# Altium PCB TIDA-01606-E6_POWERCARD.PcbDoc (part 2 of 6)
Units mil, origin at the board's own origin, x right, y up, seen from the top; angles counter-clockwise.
Board outline 13779.53 x 7874.02 mil, 4 copper layers (Top Layer, Gnd Layer, Pwr Layer, Bottom Layer), stack 94.4 mil thick; 550 components, 292 nets, 1594 pads, 572 vias.
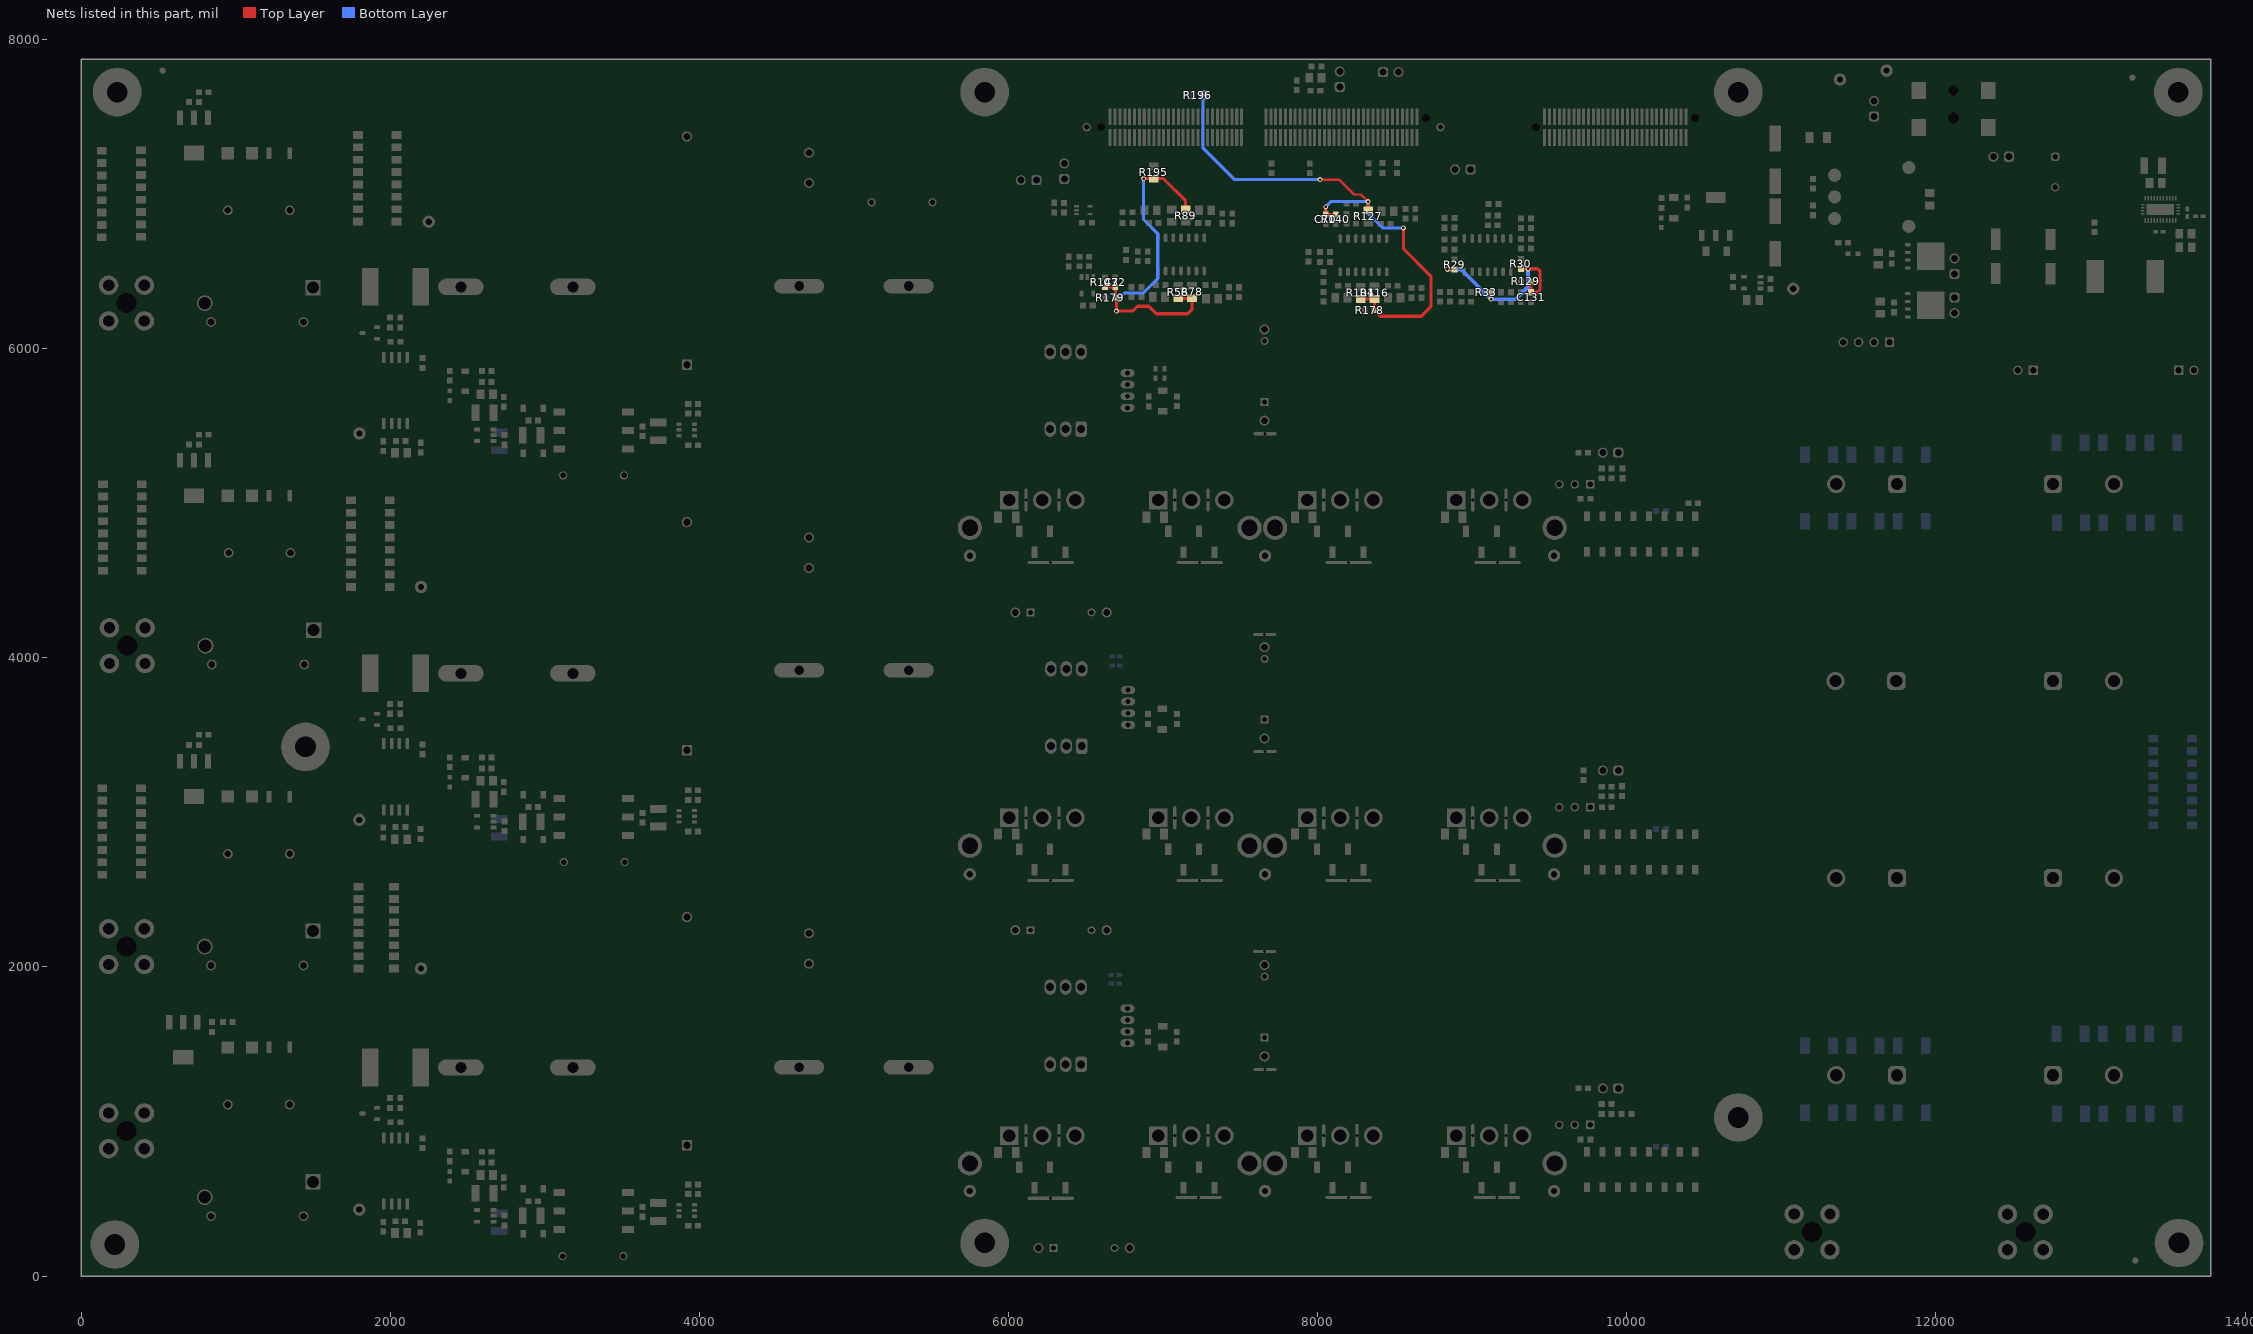
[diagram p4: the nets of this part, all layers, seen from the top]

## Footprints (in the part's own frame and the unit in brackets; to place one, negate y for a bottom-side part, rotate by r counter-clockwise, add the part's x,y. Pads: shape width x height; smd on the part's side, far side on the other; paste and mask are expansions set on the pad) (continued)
CASR [mm] "TH, 10-Leads, Body 13.4x21.91mm"
  rrect50% 1.9x2.54 hole 1.3: 1(1.37,6.35)
  oval 1.9x2.54 hole 1.3: 2(3.91,6.35) 3(6.45,6.35) 8(6.45,-6.35) 9(3.91,-6.35) 10(1.37,-6.35)
  oval 2.3x1.3 hole 0.8: 11(-6.25,-2.858) 12(-6.25,-0.953) 13(-6.25,0.952) 14(-6.25,2.857)
  body extent -7.8,-6.85 14.11,6.85, height 16.5
CE_Mark_5mm [mil] "Minimum text height for CE Mark"
  silkscreen extent -138,-98 138,98
controlCARD-120HSEC [mm] "Pads are not numbered according to Samtec datasheet."
  rect 0.5x2.724 smd: 1(-23.357,-1.678) 2(-23.357,1.722) 3(-22.557,-1.678) 4(-22.557,1.722) 5(-21.757,-1.678) 6(-21.757,1.722) 7(-20.957,-1.678) 8(-20.957,1.722) 9(-20.157,-1.678) 10(-20.157,1.722) 11(-19.357,-1.678) 12(-19.357,1.722) 13(-18.557,-1.678) 14(-18.557,1.722) 15(-17.757,-1.678) 16(-17.757,1.722) 17(-16.957,-1.678) 18(-16.957,1.722) 19(-16.157,-1.678) 20(-16.157,1.722) 21(-15.357,-1.678) 22(-15.357,1.722) 23(-14.557,-1.678) 24(-14.557,1.722) 25(-13.757,-1.678) 26(-13.757,1.722) 27(-12.957,-1.678) 28(-12.957,1.722) 29(-12.157,-1.678) 30(-12.157,1.722) 31(-11.357,-1.678) 32(-11.357,1.722) 33(-10.557,-1.678) 34(-10.557,1.722) 35(-9.757,-1.678) 36(-9.757,1.722) 37(-8.957,-1.678) 38(-8.957,1.722) 39(-8.157,-1.678) 40(-8.157,1.722) 41(-7.357,-1.678) 42(-7.357,1.722) 43(-6.557,-1.678) 44(-6.557,1.722) 45(-5.757,-1.678) 46(-5.757,1.722) 47(-4.957,-1.678) 48(-4.957,1.722) 49(-4.157,-1.678) 50(-4.157,1.722) 51(-3.357,-1.678) 52(-3.357,1.722) 53(-2.557,-1.678) 54(-2.557,1.722) 55(-1.757,-1.678) 56(-1.757,1.722) 57(2.243,-1.678) 58(2.243,1.722) 59(3.043,-1.678) 60(3.043,1.722) 61(3.843,-1.678) 62(3.843,1.722) 63(4.643,-1.678) 64(4.643,1.722) 65(5.443,-1.678) 66(5.443,1.722) 67(6.243,-1.678) 68(6.243,1.722) 69(7.043,-1.678) 70(7.043,1.722) 71(7.843,-1.678) 72(7.843,1.722) 73(8.643,-1.678) 74(8.643,1.722) 75(9.443,-1.678) 76(9.443,1.722) 77(10.243,-1.678) 78(10.243,1.722) 79(11.043,-1.678) 80(11.043,1.722) 81(11.843,-1.678) 82(11.843,1.722) 83(12.643,-1.678) 84(12.643,1.722) 85(13.443,-1.678) 86(13.443,1.722) 87(14.243,-1.678) 88(14.243,1.722) 89(15.043,-1.678) 90(15.043,1.722) 91(15.843,-1.678) 92(15.843,1.722) 93(16.643,-1.678) 94(16.643,1.722) 95(17.443,-1.678) 96(17.443,1.722) 97(18.243,-1.678) 98(18.243,1.722) 99(19.043,-1.678) 100(19.043,1.722) 101(19.843,-1.678) 102(19.843,1.722) 103(20.643,-1.678) 104(20.643,1.722) 105(21.443,-1.678) 106(21.443,1.722) 107(22.243,-1.678) 108(22.243,1.722) 109(23.043,-1.678) 110(23.043,1.722) 111(23.843,-1.678) 112(23.843,1.722) 113(24.643,-1.678) 114(24.643,1.722) 115(25.443,-1.678) 116(25.443,1.722) 117(26.243,-1.678) 118(26.243,1.722) 119(27.043,-1.678) 120(27.043,1.722)
  round 0.025 hole 1.27 unplated mask+0.876: 181(-24.857,0.022) 182(28.543,1.522)
  round 1.348 hole 0.84: 185(-27.207,0.022) 186(30.893,0.022)
  silkscreen extent -32.11,-3.86 35.8,3.9, body extent -31.75,-3.48 35.3,3.52, height 12.35
controlCARD-180HSEC-60pinAddon [mm] "Pads are not numbered according to datasheet."
  round 0.025 hole 1.27 unplated mask+0.876: 61(-13.1,0) 62(13.1,1.5)
  rect 0.5x2.724 smd: 121(-11.6,-1.7) 122(-11.6,1.7) 123(-10.8,-1.7) 124(-10.8,1.7) 125(-10,-1.7) 126(-10,1.7) 127(-9.2,-1.7) 128(-9.2,1.7) 129(-8.4,-1.7) 130(-8.4,1.7) 131(-7.6,-1.7) 132(-7.6,1.7) 133(-6.8,-1.7) 134(-6.8,1.7) 135(-6,-1.7) 136(-6,1.7) 137(-5.2,-1.7) 138(-5.2,1.7) 139(-4.4,-1.7) 140(-4.4,1.7) 141(-3.6,-1.7) 142(-3.6,1.7) 143(-2.8,-1.7) 144(-2.8,1.7) 145(-2,-1.7) 146(-2,1.7) 147(-1.2,-1.7) 148(-1.2,1.7) 149(-0.4,-1.7) 150(-0.4,1.7) 151(0.4,-1.7) 152(0.4,1.7) 153(1.2,-1.7) 154(1.2,1.7) 155(2,-1.7) 156(2,1.7) 157(2.8,-1.7) 158(2.8,1.7) 159(3.6,-1.7) 160(3.6,1.7) 161(4.4,-1.7) 162(4.4,1.7) 163(5.2,-1.7) 164(5.2,1.7) 165(6,-1.7) 166(6,1.7) 167(6.8,-1.7) 168(6.8,1.7) 169(7.6,-1.7) 170(7.6,1.7) 171(8.4,-1.7) 172(8.4,1.7) 173(9.2,-1.7) 174(9.2,1.7) 175(10,-1.7) 176(10,1.7) 177(10.8,-1.7) 178(10.8,1.7) 179(11.6,-1.7) 180(11.6,1.7)
  silkscreen extent -14.68,-3.88 14.68,3.88, body extent -14.3,-3.5 14.3,3.5, height 7.95
CUI_PJ-002AH-SMT [mm] "CUI"
  rect 2.8x2.4 smd: 1(-3.05,5.7) 1A(3.05,5.7) 2(-3.05,-5.7) 3(3.05,-5.7)
  round 1 hole 1.6 unplated: MH1(-3.05,0)
  round 1.524 hole 1.8 unplated: MH2(1.45,0)
  silkscreen extent -8.05,-4.5 6.75,5.45, body extent -8.05,-6.3 6.75,6.3, height 11.2
D0014A_N [mm] "SOIC, 14-Leads, Body 8.7x3.9mm, Pitch 1.27mm, IPC Medium Density"
  oval 1.45x0.6 smd: 1(-2.725,3.81) 2(-2.725,2.54) 3(-2.725,1.27) 4(-2.725,0) 5(-2.725,-1.27) 6(-2.725,-2.54) 7(-2.725,-3.81) 8(2.725,-3.81) 9(2.725,-2.54) 10(2.725,-1.27) 11(2.725,0) 12(2.725,1.27) 13(2.725,2.54) 14(2.725,3.81)
  silkscreen extent -3.3,-4.4 0.9,4.4, body extent -3.02,-4.32 3.02,4.32, height 1.6
DBV0005A_N [mm] "SOT23, 5-Leads, Body 2.9x1.6mm, Pitch 0.95mm, Lead Span 2.8mm, IPC Medium Density"
  rrect17% 1x0.6 smd: 1(-1.375,0.95) 2(-1.375,0) 3(-1.375,-0.95) 4(1.375,-0.95) 5(1.375,0.95)
  silkscreen extent -0.25,-1.55 0.25,1.55, body extent -1.42,-1.46 1.42,1.46, height 1.09
DBV0006A_L [mm] "SOT23, 6-Leads, Body 2.9x1.6mm, Pitch 0.95mm, Lead Span 2.8mm, IPC High Density"
  rrect18% 0.8x0.55 smd: 1(-1.275,0.95) 2(-1.275,0) 3(-1.275,-0.95) 4(1.275,-0.95) 5(1.275,0) 6(1.275,0.95)
  silkscreen extent -1.55,-1.53 0.55,1.53, body extent -1.42,-1.46 1.42,1.46, height 1.12
DCK0005A_N [mm] "SOT353, 5-Leads, Body 2x1.3mm, Pitch 0.65mm, Lead Span 2.1mm, IPC Medium Density"
  rrect25% 0.85x0.4 smd: 1(-1.125,0.65) 2(-1.125,0) 3(-1.125,-0.65) 4(1.125,-0.65) 5(1.125,0.65)
  silkscreen extent -1.48,-1.02 0.55,1.1, body extent -1.14,-1 1.14,1, height 0.95
DCY0004A_N [mm] "SOT223/SC73, 4-Leads, Body 6.5x3.5mm, Pitch 2.3mm, Lead Span 7mm, IPC Medium Density"
  rrect11% 1.75x0.9 smd: 1(-3.125,2.3) 2(-3.125,0) 3(-3.125,-2.3)
  rrect6% 1.75x3.2 smd: 4(3.125,0)
  silkscreen extent -3.02,-3.35 1.4,3.47, body extent -3.48,-3.25 3.48,3.25, height 1.68
DDC0005A_N [mm]
  rrect17% 1x0.6 smd: 1(-1.375,0.95) 2(-1.375,0) 3(-1.375,-0.95) 4(1.375,-0.95) 5(1.375,0.95)
  silkscreen extent -1.25,-1.52 0.88,1.57, body extent -1.41,-1.45 1.41,1.45, height 1.1
DQJ0008A [mm] "SMD, 8-Leads, Body 5.75x4.9mm"
  rrect39% 0.91x0.51 smd paste-0.05 mask-0.05: 1(-2.795,1.905) 2(-2.795,0.635) 3(-2.795,-0.635) 4(-2.795,-1.905) 5(2.795,-1.905) 6(2.795,-0.635) 7(2.795,0.635) 8(2.795,1.905)
  rrect8% 1.58x1.25 on Top Paste: 9(-0.38,-1.45) 9(-0.38,0) 9(-0.38,1.45) 9(1.4,-1.45) 9(1.4,0) 9(1.4,1.45)
  rrect3% 3.48x4.47 on Top Solder: 9(0.55,0)
  rrect2% 4.49x4.57 smd paste-2.5 mask-2.5: 9(1.005,0)
  silkscreen extent -3,-2.6 3,2.6, body extent -3.13,-2.45 3.13,2.45, height 1.15
DWV0008A [mm] "SOIC, 8-Leads, Body 5.95x7.6mm (max), Pitch 1.27mm"
  rrect17% 1.8x0.6 smd: 1(-5.45,1.905) 2(-5.45,0.635) 3(-5.45,-0.635) 4(-5.45,-1.905) 5(5.45,-1.905) 6(5.45,-0.635) 7(5.45,0.635) 8(5.45,1.905)
  silkscreen extent -6.25,-2.95 2.98,2.95, body extent -5.77,-2.92 5.77,2.93, height 2.67
EMC2 [mm] "Welwyn"
  round 1.6 hole 1.1: 1(-7.6,0) 2(7.6,0)
  silkscreen extent -6.42,-2 6.42,2, body extent -8.02,-2 8.02,2, height 4
ESD_Overlay_Medium [mil]
  silkscreen extent -127,-109 125,110
EUG0005A [mm] "Module, 5-Leads, Body 15.24x12.7mm"
  round 2.16 smd: 1(-6.095,3.56) 2(-6.095,0) 3(-6.095,-3.56) 4(6.095,-4.825) 5(6.095,4.825)
  silkscreen extent -8.63,-6.35 7.62,6.35, body extent -7.63,-6.35 7.62,6.35, height 8.76
FCC_disclaimer [mil]
Fiducial10-30 [mm]
  round 1 smd mask+1: 1(0,0)
  Top Layer keep-out circle w1.678: c0,0 r0.75
FP-C3M0060065D_TO-247-3-MFG [mil]
  rrect3% 120x120 hole 80 paste-39370.1 mask+0: 1(-8.37,214)
  round 120 hole 80 paste-39370.1 mask+0: 2(-8.37,0) 3(-8.37,-214)
  silkscreen extent -103,-318 103,343, body extent -99,-314 99,314, height 1004
FP-C3M0075120D_TO-247-3-MFG [mil]
  rrect3% 120x120 hole 80 paste-39370.1 mask+0: 1(-8.37,214)
  round 120 hole 80 paste-39370.1 mask+0: 2(-8.37,0) 3(-8.37,-214)
  silkscreen extent -103,-318 103,343, body extent -99,-314 99,314, height 1004
FP-ERJ-PB3B1003V_0603-MFG [mm]
  rrect15% 0.65x0.9 smd paste+0 mask+0: 1(-0.725,0) 2(0.725,0)
  silkscreen extent 0,-0.48 0,0.48, body extent -0.8,-0.4 0.8,0.4, height 0.55
FP-PSR400ITQFJ2L00_3921-MFG [mm]
  rrect4% 2.7x6.2 smd paste+0 mask+0: 1(-4.15,0) 2(4.15,0)
  silkscreen extent -2.42,-2.75 2.42,2.75, body extent -5.6,-3.2 5.6,3.2, height 0.25
HSINK_OMNI-UNI-18-50 [mm] "Heat Sink, TO-247, TO-264"
  round 4 hole 2.67: 1(-22.97,0) 2(22.97,0)
  body extent -25,-11.66 25,6.37, height 35.6
IEC_Caution_Medium [mil]
  silkscreen extent -217,-182 217,193
IEC_HighVoltage_Medium [mil]
  silkscreen extent -217,-176 217,200
IEC_HotSurface_Medium [mil]
  silkscreen extent -217,-188 217,188
Keystone5000#1 [mil] "For Keystone 500x miniature loop terminals"
  round 80 hole 40: 1(0,0)
  silkscreen extent -52,-52 52,52, body extent -49,-49 49,49, height 182
Keystone5000#2 [mil] "For Keystone 500x miniature loop terminals"
  round 80 hole 40: 1(0,-0.67)
  silkscreen extent -52,-52 52,52, body extent -49,-49 49,49, height 182
Keystone5002 [mil] "For Keystone 500x miniature loop terminals"
  round 80 hole 40: 1(0,0)
  silkscreen extent -52,-52 52,52, body extent -49,-49 49,49, height 182
Keystone24438 [mil] "Standoff, Aluminium, M3x0.5mm, L 25 mm"
  round 1 on Mech4: 0(0,0)
  body extent -98,-114 98,114, height 984
Label_650x200 [mil] "Thermal Transfer Label"
  round 1 on Mech13: 0(0,0)
  silkscreen extent -325,-100 325,100, body extent -325,-100 325,100, height 1
LP0003A [mm] "TO, Flat Index; 3 In-Line, Formed Axial Leads; Body Dia. 4.8mm; Leads 0.56 x 0.41 mm (max)"
  rrect7% 1.4x1.4 hole 0.9: 1(0,2.54)
  round 1.4 hole 0.9: 2(0,0) 3(0,-2.54)
  silkscreen extent -1.35,-2.41 2.65,2.95, body extent -1.33,-2.83 2.35,2.83, height 9.01
MiniMELF [mil] "SMD, 2-Leads, Dia 59mil"
  rect 30x75 smd: 1(-67.5,0) 2(67.5,0)
  silkscreen extent -44,-30 40,30, body extent -73,-30 73,30, height 59
Nichicon_3000x4500_Snap [mm] "TH, 2-Leads, Dia 30mm, Pin Spacing 10mm"
  rrect50% 3x3 hole 2: 1(-5,0)
  round 3 hole 2: 2(5,0)
  silkscreen extent -15.75,-15.75 15.75,15.75, body extent -15.75,-15.75 15.76,15.75, height 47.01
Pb-Free_Overlay_Medium [mil]
  silkscreen extent -95,-95 95,95
Relay_T9AS1D12 [mm] "TH, 4-Leads, Body 32.51x27.43mm"
  rect 2.5x2.5 hole 1.98: 1(-8.89,5.08)
  round 2.6 hole 2.06: 2(8.89,7.62)
  round 1.6 hole 1.09: 3(-5.08,-7.62) 4(5.08,-7.62)
  silkscreen extent -13.79,-14.73 14.15,17.79, body extent -13.26,-14.73 14.17,17.78, height 20.45
RNP0030B [mm] "QFN, 30-Leads, Body 6x4mm, Pitch 0.5mm, Thermal Pad 1.8x4.5mm"
  rrect40% 0.75x0.25 smd: 1(-1.825,2.5) 2(-1.825,2) 3(-1.825,1.5) 4(-1.825,1) 5(-1.825,0.5) 6(-1.825,0) 7(-1.825,-0.5) 8(-1.825,-1) 9(-1.825,-1.5) 10(-1.825,-2) 11(-1.825,-2.5) 16(1.825,-2.5) 17(1.825,-2) 18(1.825,-1.5) 19(1.825,-1) 20(1.825,-0.5) 21(1.825,0) 22(1.825,0.5) 23(1.825,1) 24(1.825,1.5) 25(1.825,2) 26(1.825,2.5)
  rrect40% 0.25x0.6 smd: 12(-0.75,-2.9) 13(-0.25,-2.9) 14(0.25,-2.9) 15(0.75,-2.9) 27(0.75,2.9) 28(0.25,2.9) 29(-0.25,2.9) 30(-0.75,2.9)
  rrect12% 0.8x0.94 on Top Paste: 31(-0.5,1.71) 31(-0.5,-0.57) 31(-0.5,0.57) 31(-0.5,-1.71) 31(0.5,1.71) 31(0.5,-0.57) 31(0.5,0.57) 31(0.5,-1.71)
  rrect5% 1.8x4.5 smd paste-3: 31(0,0)
  silkscreen extent -2.17,-3.18 2.18,3.17, body extent -2,-3 2,3, height 0.8
Samtec_SSW-102-01-x-S [mm] "Receptacle, 2x1, 2.54mm, TH"
  rect 1.55x1.55 hole 1.04: 1(-1.27,0)
  round 1.55 hole 1.04: 2(1.27,0)
  silkscreen extent -3.1,-1.21 2.79,1.21, body extent -2.79,-1.21 2.8,1.2, height 8.51
SMA [mm] "Molded Diode, 2-Leads, Body 4.3x2.6mm, IPC Medium Density, based on OnSemi component dimensions and land pattern"
  rect 2x2 smd: 1(-2,0) 2(2,0)
  silkscreen extent -3.66,-1.57 2.79,1.57, body extent -2.6,-1.3 2.6,1.3, height 2.42
SOD-123 [mm] "On Semi recommended land pattern"
  rect 0.915x1.22 smd: 1(-1.637,0) 2(1.637,0)
  silkscreen extent -2.74,-1.17 2.03,1.17, body extent -1.93,-0.9 1.93,0.9, height 1.35
SOT-23 [mm] "SOT23, 3-Leads, Body 2.9x1.3mm, Pitch 0.95mm, Lead Span 2.5mm, IPC Medium Density"
  rrect50% 1x0.6 smd: 1(-1.2,0.95) 2(-1.2,-0.95) 3(1.2,0)
  silkscreen extent -1.62,-1.5 0.7,1.5, body extent -1.16,-1.45 1.21,1.45, height 1
SOT-223 [mm] "SOT223/SC73, 4-Leads, Body 6.5x3.5mm, Pitch 2.3mm, Lead Span 7mm, IPC Medium Density"
  rrect10% 2.4x1 smd: 1(-2.9,2.3) 2(-2.9,0) 3(-2.9,-2.3)
  rrect4% 2.4x3.3 smd: 4(2.9,0)
  silkscreen extent -3.33,-3.35 1.4,3.35, body extent -3.5,-3.25 3.5,3.25, height 1.62
SQM_7 [mm] "TH, 2-Leads, Body 13x9mm, Pin Spacing 5mm"
  round 1.65 hole 1.1: 1(-2.5,0) 2(2.5,0)
  silkscreen extent -7,-5.25 7,5.25, body extent -7,-5.25 7,5.25, height 40
Sullins_xPxC041KFXC-RC [mm] "Receptacle, 2.54mm, 4x1, SMT"
  rrect10% 1x1.9 smd: 1(-3.81,1.7) 2(-1.27,-1.7) 3(1.27,1.7) 4(3.81,-1.7)
  body extent -5.08,-2.15 5.08,2.15, height 7.5
Sullins_xPxC041LFBN [mm] "Receptacle, 2.54mm, 4x1, TH"
  rect 1.55x1.55 hole 1.02: 1(-3.81,0)
  round 1.55 hole 1.02: 2(-1.27,0) 3(1.27,0) 4(3.81,0)
  silkscreen extent -5.33,-1.27 5.33,1.6, body extent -5.33,-1.27 5.33,1.27, height 8.5
Sullins_xPxC082KFMS-RC [mm] "Receptacle, 2.54mm, 8x2, SMT"
  rrect10% 1x1.56 smd: 1(-8.89,2.905) 2(-8.89,-2.905) 3(-6.35,2.905) 4(-6.35,-2.905) 5(-3.81,2.905) 6(-3.81,-2.905) 7(-1.27,2.905) 8(-1.27,-2.905) 9(1.27,2.905) 10(1.27,-2.905) 11(3.81,2.905) 12(3.81,-2.905) 13(6.35,2.905) 14(6.35,-2.905) 15(8.89,2.905) 16(8.89,-2.905)
  body extent -10.41,-3.42 10.41,3.42, height 7.5
VY1_900x500x1300 [mm] "TH, Body 9x5mm, PinSpacing 10mm"
  round 1.35 hole 0.9: 1(-5,0) 2(5,0)
  body extent -5.4,-2.5 5.4,2.5, height 12.93
WCAP-ASLL_800x1050 [mm] "SMD, 2-Leads, Dia 8mm"
  rrect5% 4.2x1.9 smd: 1(-3.5,0) 2(3.5,0)
  body extent -4.3,-4.25 4.3,4.25, height 10.51
WCAP-ATLI_1000x1600 [mm] "TH, 2-Leads, Dia 10mm, Pin Spacing 5mm"
  rrect50% 1.35x1.35 hole 0.9: 1(-2.5,0)
  round 1.35 hole 0.9: 2(2.5,0)
  body extent -5.25,-5.25 5.26,5.25, height 17.51
WCAP-FTBP_1800x700x1300 [mm] "TH, 2-Leads, Body 18x7mm, Lead Spacing 15mm"
  round 1.65 hole 1.1: 1(-7.5,0) 2(7.5,0)
  body extent -9.75,-4 9.75,4, height 14
WCAP-PSLP_630x580 [mm] "SMD, 2-Leads, Dia 6.3mm"
  rect 3.5x1.6 smd: 1(-2.8,0) 2(2.8,0)
  silkscreen extent -3.4,-3.4 3.4,3.4, body extent -3.4,-3.4 3.4,3.4, height 5.81
WE-PD_1210 [mm] "Wurth Elektronik recommended land pattern"
  rect 2.9x5.4 smd: 1(-4.95,0) 2(4.95,0)
  silkscreen extent -6,-6 6,6, body extent -6,-6 6,6, height 10.01
WEEE_Minimum [mil] "WEEElie bin"
  silkscreen extent -95,-172 99,104
WL-SMCD-0603 [mm] "SMD, 2-Leads, Body 1.6x0.8mm"
  rrect13% 0.8x0.75 smd: 1(-0.8,0) 2(0.8,0)
  body extent -0.8,-0.4 0.8,0.4, height 0.4
Wurth_750313638 [mm] "SMD, 6-Leads, Body 8x9.14mm, Pitch 3.05mm"
  rect 1.9x1.14 smd: 1(-5.655,3.05) 2(-5.655,0) 3(-5.655,-3.05) 4(5.655,-3.05) 5(5.655,0) 6(5.655,3.05)
  silkscreen extent -4,-4.57 4,4.87, body extent -6.35,-4.57 6.35,4.57, height 7.62
WURTH_61300211121 [mm] "Header, 2.54mm, 2x1, TH"
  rrect50% 1.65x1.65 hole 1.15: 1(-1.27,0)
  round 1.65 hole 1.15: 2(1.27,0)
  body extent -2.54,-1.27 2.54,1.27, height 8.54
Wurth_WP-THRBU [mm] "Power Element Bush, M3, TH"
  round 3.2 hole 1.85: 1(-2.935,-2.935) 1(-2.935,2.935) 1(2.935,-2.935) 1(2.935,2.935)
  round 3.1 on Top Paste: ""(-2.935,-2.935) ""(-2.935,2.935) ""(2.935,-2.935) ""(2.935,2.935)
  round 3 hole 3.3 unplated mask+0.102: ""(0,0)
  silkscreen extent -3.5,-3.5 3.5,3.5, body extent -3.5,-3.5 3.5,3.5, height 3

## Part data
C1 C2 C3 C11 C12 C13: library part CMP-0081646-1, "CAP, Film, 0.15 µF, 630 V,+/- 5%, 0.06122 ohm, TH", Cap_Case=18x7x13mm, Manufacturer="Wurth Elektronik", Supplier Part Number 1=732-11835-ND, Tolerance_%=5%, Value1="0.06122 ohm", Value2=630V, ValueDisplayed=0.15µF
C4 C5 C6 C7 C73 C74 C75 C76: library part CMP-0010058-3, "CAP, AL, 120 uF, 600 V, +/- 20%, TH", Cap_Case=30x45mm, Manufacturer=Nichicon, Supplier Part Number 1=493-14690-ND, Tolerance_%=20%, Value1=Unknown, Value2=600V, ValueDisplayed=120uF
C8 C9 C10: library part CMP-0083863-1, "CAP, Film, 10 µF,  V,+/- 10%, AEC-Q200 Grade 1, TH", Cap_Case=41.5x28mm, Manufacturer=TDK, Supplier Part Number 1=495-4794-ND, Tolerance_%=10%, ValueDisplayed=10µF
C14 C18 C21 C23 C25 C28 C29 C32 C35 C36 C39 C40 C41 C42 C44 C45 C46 C47 C50 C51 C52 C53 C54 C55 C57 C59 C60 C63 C69 C70 C71 C72 C90 C91 C92 C131 C132 C134 C135: library part CMP-0006979-5, "CAP, CERM, 0.1 uF, 25 V, +/- 10%, X7R, 0603", Cap_Case=0603, Manufacturer=Kemet, Supplier Part Number 1=399-5345-1-ND, TempCo=X7R, Tolerance_%=10%, Value1=Unknown, Value2=25V, ValueDisplayed=0.1uF
C15 C20 C30 C38: library part CMP-0008132-2, "CAP, CERM, 2.2 uF, 10 V, +/- 10%, X5R, 0805", Cap_Case=0805, Manufacturer=MuRata, Supplier Part Number 1=490-1704-1-ND, TempCo=X5R, Tolerance_%=10%, Value1="0.009 ohm", Value2=10V, ValueDisplayed=2.2uF
C16 C17 C93 C95 C97 C98 C105 C106 C107 C110 C112 C116: library part CMP-0009233-2, "CAP, CERM, 10 uF, 35 V, +/- 10%, X7R, 1210", Cap_Case=1210, Manufacturer=MuRata, Supplier Part Number 1=490-5314-1-ND, TempCo=X7R, Tolerance_%=10%, Value1=Unknown, Value2=35V, ValueDisplayed=10uF
C19: library part CMP-0006551-2, "CAP, CERM, 0.47 uF, 6.3 V, +/- 10%, X5R, 0402", Cap_Case=0402, Manufacturer=MuRata, Supplier Part Number 1=490-3266-1-ND, TempCo=X5R, Tolerance_%=10%, Value1=Unknown, Value2=6.3V, ValueDisplayed=0.47uF
C22 C24 C31 C43 C49: library part CMP-0080740-1, "CAP, CERM, 10 µF, 25 V,+/- 10%, X7R, 1206", Cap_Case=1206, Manufacturer=TDK, Supplier Part Number 1=445-7705-1-ND, TempCo=X7R, Tolerance_%=10%, Value2=25V, ValueDisplayed=10µF
C26 C27 C33 C34 C64 C66 C94 C96 C99 C100 C103 C104 C108 C109 C111 C113 C115: library part CMP-0079602-1, "CAP, CERM, 0.1 µF, 50 V,+/- 10%, X7R, AEC-Q200 Grade 1, 0603", Cap_Case=0603, Manufacturer=Kemet, Supplier Part Number 1=399-6856-1-ND, TempCo=X7R, Tolerance_%=10%, Value2=50V, ValueDisplayed=0.1µF
C37 C56 C58 C117: library part CMP-0006867-4, "CAP, CERM, 1 uF, 25 V, +/- 10%, X7R, 0603", Cap_Case=0603, Manufacturer=Kemet, Supplier Part Number 1=399-7376-1-ND, TempCo=X7R, Tolerance_%=10%, Value1=Unknown, Value2=25V, ValueDisplayed=1uF
C48 C126: library part CMP-0081645-1, "CAP, Aluminum Polymer, 33 µF, 20 V,+/- 20%, 0.03 ohm, D6.3xL5.8mm SMD", Cap_Case=6.3x5.8mm, Manufacturer="Wurth Elektronik", Supplier Part Number 1=732-6430-1-ND, Tolerance_%=20%, Value1="0.03 ohm", Value2=20V, ValueDisplayed=33µF
C61 C62: library part CMP-0081644-1, "CAP, AL, 100 µF, 50 V, +/- 20%, SMD", Cap_Case=8X10.5mm, Manufacturer="Wurth Elektronik", Supplier Part Number 1=732-8550-1-ND, Tolerance_%=20%, Value2=50V, ValueDisplayed=100µF
C65 C67 C68: library part CMP-0086097-1, "CAP, CERM, 1000 pF, X1 760 VAC/Y1 500 VAC, +/- 20%, Y5U, 9x5mm", Cap_Case=9X5mm, Manufacturer=Vishay-Bccomponents, TempCo=Y5U, Tolerance_%=20%, ValueDisplayed=1000pF
C77 C79 C81 C118: library part CMP-0083857-1, "CAP, CERM, 100 pF, 50 V,+/- 10%, X7R, 0603", Cap_Case=0603, Manufacturer="Samsung Electro-Mechanics", TempCo=X7R, Tolerance_%=10%, Value2=50V, ValueDisplayed=100pF
C78 C80 C82: library part CMP-0006799-4, "CAP, CERM, 82 pF, 50 V, +/- 5%, C0G/NP0, 0603", Cap_Case=0603, Manufacturer=AVX, Supplier Part Number 1=478-1174-1-ND, TempCo=C0G/NP0, Tolerance_%=5%, Value1="0.131 ohm", Value2=50V, ValueDisplayed=82pF
C83 C84 C85 C86 C87 C88 C133: library part CMP-0006762-4, "CAP, CERM, 100 pF, 50 V, +/- 1%, C0G/NP0, 0603", Cap_Case=0603, Manufacturer=AVX, Supplier Part Number 1=478-6202-1-ND, TempCo=C0G/NP0, Tolerance_%=1%, Value1=Unknown, Value2=50V, ValueDisplayed=100pF
C89: library part CMP-0081643-1, "CAP, AL, 220 µF, 50 V, +/- 20%, TH", Cap_Case=10x16mm, Manufacturer="Wurth Elektronik", Supplier Part Number 1=732-9057-1-ND, Tolerance_%=20%, Value2=50V, ValueDisplayed=220µF
C101 C102 C114 C125: library part CMP-0008309-2, "CAP, CERM, 4.7 uF, 50 V, +/- 10%, X5R, 0805", Cap_Case=0805, Manufacturer=MuRata, Supplier Part Number 1=GRM21BR61H475KE51L-ND, TempCo=X5R, Tolerance_%=10%, Value1=Unknown, Value2=50V, ValueDisplayed=4.7uF
C119: library part CMP-0083861-1, "CAP, CERM, 0.47 µF, 50 V,+/- 10%, X5R, 0603", Cap_Case=0603, Manufacturer=MuRata, Supplier Part Number 1=490-11994-1-ND, TempCo=X5R, Tolerance_%=10%, Value2=50V, ValueDisplayed=0.47µF
C120 C121 C122 C127 C128 C129: library part CMP-0012400-3, "CAP, Film, 0.068 uF, 630 V, +/- 10%, TH", Manufacturer=TDK, Supplier Part Number 1=1781890, Tolerance_%=10%, Value1=Unknown, Value2=630V, ValueDisplayed=0.068uF
C123: library part CMP-0082268-1, "CAP, CERM, 4.7 µF, 100 V,+/- 10%, X7S, AEC-Q200 Grade 1, 1210", Cap_Case=1210, Manufacturer=MuRata, Supplier Part Number 1=490-14484-1-ND, TempCo=X7S, Tolerance_%=10%, Value1="0.001 ohm", Value2=100V, ValueDisplayed=4.7µF
C124: library part CMP-0008373-2, "CAP, CERM, 0.047 uF, 100 V, +/- 10%, X7R, 0805", Cap_Case=0805, Manufacturer=MuRata, Supplier Part Number 1=490-3325-1-ND, TempCo=X7R, Tolerance_%=10%, Value1=Unknown, Value2=100V, ValueDisplayed=0.047uF
C130: library part CMP-0009601-2, "CAP, CERM, 2200 pF, 3KV, +/- 20%, E, Cap, 7x12x9 mm", Cap_Case=CAPRD1000W60D900H1200, Manufacturer=MuRata, Supplier Part Number 1=490-7047-ND, TempCo=E, Tolerance_%=20%, Value1=Unknown, Value2=250V, ValueDisplayed=2200pF
D1 D2 D4 D5: library part CMP-0006039-4, "Diode, Zener, 15 V, 500 mW, MiniMELF", Manufacturer="Micro Commercial Components", Power_W=500mW, Value1=0.5W
D3 D6 D7 D8: library part CMP-0028389-2, "Diode, Schottky, 60 V, 1 A, SMA", Manufacturer="Diodes Inc.", Value1=1A, Value2=0.7V
D9 D11 D24 D25 D30 D31: library part CMP-0080707-2, "Diode, Schottky, 20 V, 0.5 A, SOD-123", Manufacturer="Diodes Inc.", Value1=0.5A, Value2=0.33V
D12 D14 D16: library part CMP-0005922-4, "Diode, TVS, Uni, 27 V, SOT-23", Manufacturer="ON Semiconductor", Value1=40W
D13 D15 D17: library part CMP-0005926-4, "Diode, TVS, Uni, 33 V, 46 Vc, SOT-23", Manufacturer="ON Semiconductor", Value1=40W
D18 D19 D26 D27 D32: library part CMP-0081648-2, "LED, Green, SMD", Color=Green, Manufacturer="Wurth Elektronik", Power_TotalModule=48mW, Value1=0.048W, Value2=2V
D28 D29 D33: library part CMP-0005803-3, "Diode, Zener, 5.6 V, 500 mW, SOD-123", Manufacturer="Diodes Inc.", Power_W=500mW, Value1=0.5W
FID1 FID2 FID3 FID4 FID5 FID6: library part CMP-0077181-1, "Fiducial mark.  There is nothing to buy or mount.", Manufacturer=N/A
GND_1 GND_2 GND_3 TP1 TP4 TP5 TP6 TP7 TP8 TP9 TP10 TP11 TP12 TP13 TP14 TP15: library part CMP-0055137-1, "Test Point, Miniature, Red, TH", Color=Red, Manufacturer=Keystone, Supplier Part Number 1=36-5000-ND
H1 H2 H3 H4 H9 H10 H11 H12 H13: library part CMP-0003646-1, "MACHINE SCREW PAN PHILLIPS M3 5mm", Manufacturer="B&F Fastener Supply", Supplier Part Number 1=H742-ND
H5 H6 H7 H8 H14 H15 H16 H17 H18: library part CMP-0003640-1, "Standoff, Hex,25mm Length, M3, Aluminum", Manufacturer=Keystone, Supplier Part Number 1=36-24438-ND
H19 H20 H21 H22 H23 H24: library part CMP-0079407-1, "Heat Sink, TO-247, TO-264, Vertical", Manufacturer=Wakefield-Vette, Supplier Part Number 1=345-1486-ND
J1 J2 J3 J4 J31 J32: library part CMP-0078526-1, "Power Element Bush, M3, TH", Current_A=50A, Manufacturer="Wurth Elektronik", Supplier Part Number 1=732-10882-1-ND
J5: library part CMP-0003814-2, "C2000 controlCARD-120HSEC connector, SMT", Manufacturer=Samtec
J6 J8 J10 J11 J26 J27 J28 J29 J30 J34 J37 J39: library part CMP-0054794-2, "Header, 2.54 mm, 2x1, Gold, TH", Color=Black, Manufacturer="Wurth Elektronik", Supplier Part Number 1=732-5315-ND
J7 J9 J12 J14 J15 J16 J17 J18 J19 J20 J21 J22: library part CMP-0083775-2, "Receptacle, 2.54mm, 4x1, Tin, SMT", Color=Black, Current_A=3A, Manufacturer="Sullins Connector Solutions", Supplier Part Number 1=S5596-ND, Voltage_V=250V
J13: library part CMP-0003859-2, "C2000 controlCARD-180HSEC (60-pin addon) connector, SMT", Manufacturer=Samtec, Supplier Part Number 1=SAM9080-ND
J23 J24 J25: library part CMP-0083774-2, "Receptacle, 2.54mm, 8x2, Tin, SMT", Color=Black, Current_A=3A, Manufacturer="Sullins Connector Solutions", Supplier Part Number 1=S5678-ND, Voltage_V=250V
J33: library part CMP-0075012-1, "Power Jack, SMT", Manufacturer="CUI Inc.", Supplier Part Number 1=CP-002AHPJDKR-ND
J35 J36: library part CMP-0075620-1, "Receptacle, 2x1, 2.54mm, Tin, TH", Color=Black, Current_A=5.7A, Manufacturer=Samtec, Supplier Part Number 1=SAM1213-02-ND
J38: library part CMP-0054676-1, "Receptacle, 2.54mm, 4x1, Tin, TH", Color=Black, Current_A=3A, Manufacturer="Sullins Connector Solutions", Supplier Part Number 1=S7002-ND, Voltage_V=250V
K1 K2 K3 K4: library part CMP-0078608-2, "Relay, SPST-NO (1 Form A), 30 A, 15 V, TH", Coil Current_A=66.7mA, Coil Power_W=1W, Coil Resistance_ohm=225, Coil Voltage_VDC=15V, Contact Rating_A=30A, Manufacturer="TE Connectivity", Turn Off Voltage (Min)_VDC=1.5V, Turn On Voltage (Max)_VDC=11.25V
L1 L3 L5: library part CMP-0082074-1, "Inductor, Toroid, 340 µH, 15 A, 0.05 ohm, TH", Manufacturer="Wurth Elektronik", Value1="0.05 ohm", Value2=15A, ValueDisplayed=340µH
L2 L4 L6: library part CMP-0082075-1, "Inductor, Toroid, 15 A, 0.006 ohm, TH", Manufacturer="Wurth Elektronik", Value1="0.006 ohm", Value2=15A
L7 L8 L9 L10 L13 L14 L17 L21 L23: library part CMP-0003155-2, "Ferrite Bead, 26 ohm @ 100 MHz, 6.5 A, 0603", Manufacturer="Wurth Elektronik", Supplier Part Number 1=732-6117-1-ND, Value1="0.005 ohm", Value2=6.5A, ValueDisplayed="26 ohm"
L11 L12 L15: library part CMP-0003201-2, "Ferrite Bead, 1000 ohm @ 100 MHz, 0.6 A, 0603", Manufacturer="Wurth Elektronik", Supplier Part Number 1=732-4670-1-ND, Value1="0.3 ohm", Value2=0.6A, ValueDisplayed="1000 ohm"
L16: library part CMP-0064538-2, "Inductor, Shielded Drum Core, Ferrite, 22 uH, 5.3 A, 0.0233 ohm, SMD", Manufacturer="Wurth Elektronik", Supplier Part Number 1=732-1243-1-ND, Value1="0.0233 ohm", Value2=5.3A, ValueDisplayed=22uH
L19: library part CMP-0003139-1, "Ferrite Bead, 110 ohm @ 100 MHz, 5.4 A, 1206", Manufacturer="Wurth Elektronik", Supplier Part Number 1=732-6130-1-ND, Value1="0.0095 ohm", Value2=5.4A, ValueDisplayed="110 ohm"
LBL1: library part CMP-0003625-1, "Thermal Transfer Printable Labels, 0.650\" W x 0.200\" H - 10,000 per roll", Manufacturer=Brady, Supplier Part Number 1=97C5133
LOGO1: library part CMP-0074844-1
Logo2: library part CMP-0074839-1
Logo3: library part CMP-0074847-1, "FCC_disclaimer"
Logo4: library part CMP-0074836-1, "IEC 61010-1 Caution Warning"
Logo5: library part CMP-0074840-1, "ESD Susceptible Symbol"
LOGO6 LOGO11 LOGO12: library part CMP-0074837-1, "IEC 61010-1 Hot Surface Warning"
LOGO7 LOGO8 LOGO9 LOGO10 LOGO13: library part CMP-0074835-1, "IEC 61010-1 High Voltage Warning"
Logo14: library part CMP-0074769-1
Q1 Q2 Q5 Q6 Q9 Q10: library part CMP-0097459-1, "N-Channel 1200 V 30A (Tc) 113.6W (Tc) Through Hole TO-247-3", Digikey Part Number=1697-C3M0075120D-ND, Drain To Source Breakdown Voltage=1200V, Input Capacitace At Vds="1390pF @ 1000V", Manufacturer=Wolfspeed, Mouser Part Number=941-C3M0075120D, Operating Temperature Range="-40°C to +175°C", Power_W=136W, Pulse Drain Current=80A, Typ Forward Diode Voltage=4.5V
Q3 Q4 Q7 Q8 Q11 Q12: library part CMP-0097458-1, "N-Channel 650 V 37A (Tc) 150W (Tc) Through Hole TO-247-3", Digikey Part Number=1697-C3M0060065D-ND, Drain To Source Breakdown Voltage=650V, Input Capacitace At Vds="1020pF @ 600V", Manufacturer=Wolfspeed, Mouser Part Number=941-C3M0060065D, Operating Temperature Range="-40°C to +175°C", Power_W=150W, Pulse Drain Current=99A, Typ Forward Diode Voltage=5.1V
Q13 Q14: library part CMP-0000817-1, "MOSFET, N-CH, 60 V, 50 A, DQJ0008A (VSONP-8)", Alternate Manufacturer=None, Manufacturer="Texas Instruments", Supplier Part Number 1=296-35583-1-ND, Value1=0.009, Value2="22 nC"
Q15 Q16 Q17 Q18: library part CMP-0081320-1, "MOSFET, N-CH, 60 V, 4 A, SOT-223", Alternate Manufacturer=None, Manufacturer="ON Semiconductor", Supplier Part Number 1=NDT3055LCT-ND, Value1="0.12 ohm", Value2="13 nC"
R1 R2 R3 R4 R6 R7 R9 R10 R12 R13 R14 R15 R180 R181 R182 R183 R184 R185 R186 R187 R188 R189 R190 R191: library part CMP-0016151-3, "RES, 510 k, 5%, 0.75 W, AEC-Q200 Grade 0, 2010", Manufacturer=Vishay-Dale, Power_W=750mW, Supplier Part Number 1=541-510KWCT-ND, TempCo="200 ppm/C", Tolerance_%=5%, Value2=0.75W, Value_Code=510k
R5 R41 R47: library part CMP-0097460-1, "2 mOhms ±1% 4W Chip Resistor Nonstandard Automotive AEC-Q200, Current Sense Metal Element", Digikey Part Number=RHM1677-CT-ND, Manufacturer=Rohm, Mouser Part Number=755-PSR400ITQFJ2L00, Operating Temperature Range="-65°C to +175°C", Power_W=6W, TempCo=0/+75ppm/°C, Tolerance_%=1%
R8 R11 R32 R37 R52 R55 R58 R60 R62 R64 R65 R76 R77 R91 R92 R93 R167: library part CMP-0022684-3, "RES, 10.0 k, 1%, 0.1 W, 0603", Manufacturer=Panasonic, Power_W=100mW, Supplier Part Number 1=P10.0KHCT-ND, TempCo="100 ppm/C", Tolerance_%=1%, Value2=0.1W, Value_Code=10k0, ValueDisplayed=10.0k
R16 R17 R18: library part CMP-0078524-1, "RES, 0.68, 5%, 7 W, 13x9mm", Manufacturer="TE Connectivity", Power_W=7W, Supplier Part Number 1=A103699-ND, TempCo="300 ppm/C", Tolerance_%=5%, Value_Code=R680, ValueDisplayed=0.68
R19 R20 R21 R22 R23 R24: library part CMP-0092407-1, "Res Thick Film 0603 100K Ohm 0.1% 0.2W(1/5W) ±50ppm/°C Pad SMD Automotive T/R", Digikey Part Number=P20200CT-ND, Manufacturer=Panasonic, Mouser Part Number=667-ERJ-PB3B1003V, Operating Temperature Range="-55°C to +155°C", Power_W=200mW, TempCo=50ppm/°C, Tolerance_%=0.1%
R25 R26 R29 R30 R31 R33: "RES, 100 k, 1%, 0.1 W, 0603", Manufacturer=Vishay-Dale, Power_W=0.1, Supplier Part Number 1=541-100KHCT-ND, TempCo="100 ppm/C", Tolerance_%=1, Value1=1%, Value2=0.1W, Value_Code=100k
R27 R28 R38 R40 R46 R71 R84 R99 R111 R122 R136: library part CMP-0022553-4, "RES, 68.1, 1%, 0.1 W, AEC-Q200 Grade 0, 0603", Manufacturer=Vishay-Dale, Power_W=100mW, Supplier Part Number 1=541-68.1HCT-ND, TempCo="100 ppm/C", Tolerance_%=1%, Value2=0.1W, Value_Code=68R1, ValueDisplayed=68.1
R34 R36 R163 R164 R165: library part CMP-0081973-1, "RES, 0, 0%, 0.25 W, AEC-Q200 Grade 0, 0603", Manufacturer=Vishay-Dale, Power_W=250mW, Supplier Part Number 1=541-2779-1-ND, Tolerance_%=0%, Value2=0.25W, Value_Code=0
R35: library part CMP-0020539-3, "RES, 3.3 k, 5%, 0.125 W, AEC-Q200 Grade 0, 0805", Manufacturer=Vishay-Dale, Power_W=125mW, Supplier Part Number 1=541-3.3KACT-ND, TempCo="200 ppm/C", Tolerance_%=5%, Value2=0.125W, Value_Code=3k30, ValueDisplayed=3.3k
R39 R56 R61 R78 R79 R89 R94 R104 R105 R116 R117 R127 R131 R206: library part CMP-0018864-2, "RES, 11.0 k, 0.1%, 0.125 W, 0805", Manufacturer="Susumu Co Ltd", Power_W=125mW, Supplier Part Number 1=RG20P11.0KBCT-ND, TempCo="25 ppm/C", Tolerance_%=0.1%, Value2=0.125W, Value_Code=11k0, ValueDisplayed=11.0k
R42 R43 R44 R48 R49 R50 R67 R68 R69 R73 R74 R80 R81 R82 R85 R86 R87 R95 R96 R97 R100 R101 R102 R106 R107 R108 R110 R112 R113 R114 R118 R119 R120 R123 R124 R125 R132 R133 R134 R137 R138 R166: library part CMP-0019761-2, "RES, 1.00 M, 0.1%, 0.125 W, 0805", Manufacturer="Yageo America", Power_W=125mW, Supplier Part Number 1=603-RT0805BRD071ML, TempCo="25 ppm/C", Tolerance_%=0.1%, Value2=0.125W, Value_Code=1M00, ValueDisplayed=1.00M
R45 R51 R70 R75 R83 R88 R98 R103 R109 R115 R121 R126 R135 R205: library part CMP-0019726-2, "RES, 1.00 k, 0.1%, 0.125 W, 0805", Manufacturer="Yageo America", Power_W=125mW, Supplier Part Number 1=603-RT0805BRD071KL, TempCo="25 ppm/C", Tolerance_%=0.1%, Value2=0.125W, Value_Code=1k00, ValueDisplayed=1.00k
R53 R63 R90 R154 R155 R157 R159 R160 R161: library part CMP-0025874-4, "RES, 0, 5%, 0.1 W, AEC-Q200 Grade 0, 0603", Manufacturer=Panasonic, Power_W=100mW, Supplier Part Number 1=P0.0GCT-ND, TempCo="600 ppm/C", Tolerance_%=5%, Value2=0.1W, Value_Code=0000, ValueDisplayed=0
R54: library part CMP-0025950-3, "RES, 100 k, 1%, 0.063 W, AEC-Q200 Grade 0, 0402", Manufacturer=Vishay-Dale, Power_W=63mW, Supplier Part Number 1=541-100KLCT-ND, TempCo="100 ppm/C", Tolerance_%=1%, Value2=0.063W, Value_Code=100k
R57: library part CMP-0026619-3, "RES, 9.09 k, 1%, 0.063 W, AEC-Q200 Grade 0, 0402", Manufacturer=Vishay-Dale, Power_W=63mW, Supplier Part Number 1=541-9.09KLCT-ND, TempCo="100 ppm/C", Tolerance_%=1%, Value2=0.063W, Value_Code=9k09, ValueDisplayed=9.09k
R59 R66: library part CMP-0021039-3, "RES, 200, 1%, 0.125 W, AEC-Q200 Grade 0, 0805", Manufacturer=Vishay-Dale, Power_W=125mW, Supplier Part Number 1=541-200CCT-ND, TempCo="100 ppm/C", Tolerance_%=1%, Value2=0.125W, Value_Code=200R, ValueDisplayed=200
R72: library part CMP-0020527-3, "RES, 330, 5%, 0.125 W, AEC-Q200 Grade 0, 0805", Manufacturer=Vishay-Dale, Power_W=125mW, Supplier Part Number 1=541-330ACT-ND, TempCo="200 ppm/C", Tolerance_%=5%, Value2=0.125W, Value_Code=330R, ValueDisplayed=330
R128 R130 R139 R141 R142 R144: library part CMP-0023404-3, "RES, 10.0 k, 0.1%, 0.1 W, 0603", Manufacturer="Susumu Co Ltd", Power_W=100mW, Supplier Part Number 1=RG16P10.0KBCT-ND, TempCo="25 ppm/C", Tolerance_%=0.1%, Value2=0.1W, Value_Code=10k0, ValueDisplayed=10.0k
R129 R140 R143 R178 R179: library part CMP-0025703-4, "RES, 10, 5%, 0.1 W, AEC-Q200 Grade 0, 0603", Manufacturer=Vishay-Dale, Power_W=100mW, Supplier Part Number 1=541-10GCT-ND, TempCo="200 ppm/C", Tolerance_%=5%, Value2=0.1W, Value_Code=10R0, ValueDisplayed=10
R145 R147 R148 R150 R151 R153: library part CMP-0021995-5, "RES, 105, 1%, 0.1 W, AEC-Q200 Grade 0, 0603", Manufacturer=Vishay-Dale, Power_W=100mW, Supplier Part Number 1=541-105HCT-ND, TempCo="100 ppm/C", Tolerance_%=1%, Value2=0.1W, Value_Code=105R, ValueDisplayed=105
R146 R149 R152: library part CMP-0023039-4, "RES, 33.0, 1%, 0.1 W, 0603", Manufacturer=Yageo, Power_W=100mW, Supplier Part Number 1=311-33.0HRCT-ND, TempCo="100 ppm/C", Tolerance_%=1%, Value2=0.1W, Value_Code=33R0, ValueDisplayed=33.0
R156 R158 R162 R207 R208: library part CMP-0023288-5, "RES, 820, 1%, 0.1 W, 0603", Manufacturer=Yageo, Power_W=100mW, Supplier Part Number 1=311-820HRCT-ND, TempCo="100 ppm/C", Tolerance_%=1%, Value2=0.1W, Value_Code=820R, ValueDisplayed=820
R168 R169 R170 R171 R172 R173 R174 R175 R176 R192 R193 R194: library part CMP-0018576-3, "RES, 10 k, 5%, 0.25 W, AEC-Q200 Grade 0, 1206", Manufacturer=Vishay-Dale, Power_W=250mW, Supplier Part Number 1=541-10KECT-ND, TempCo="200 ppm/C", Tolerance_%=5%, Value2=0.25W, Value_Code=10k0, ValueDisplayed=10k
R177 R195 R196: library part CMP-0020616-3, "RES, 0, 5%, 0.125 W, AEC-Q200 Grade 0, 0805", Manufacturer=Panasonic, Power_W=125mW, Supplier Part Number 1=P0.0ACT-ND, TempCo="600 ppm/C", Tolerance_%=5%, Value2=0.125W, Value_Code=0000, ValueDisplayed=0
R197 R198 R199 R200: library part CMP-0025882-3, "RES, 100, 5%, 0.25 W, AEC-Q200 Grade 0, 0603", Manufacturer=Rohm, Power_W=250mW, Supplier Part Number 1=RHM100DCT-ND, TempCo="200 ppm/C", Tolerance_%=5%, Value2=0.25W, Value_Code=100R, ValueDisplayed=100
R201 R202 R203 R204: library part CMP-0025768-4, "RES, 2.0 k, 5%, 0.1 W, AEC-Q200 Grade 0, 0603", Manufacturer=Vishay-Dale, Power_W=100mW, Supplier Part Number 1=541-2.0KGCT-ND, TempCo="200 ppm/C", Tolerance_%=5%, Value2=0.1W, Value_Code=2k00, ValueDisplayed=2.0k
RF1 RF2 RF3 RF4: library part CMP-0014288-1, "RES, 47, 10%, 2 W, Axial resistor", Manufacturer="TT Electronics/IRC", Power_W=2W, Supplier Part Number 1=985-1022-1-ND, TempCo="100 ppm/C", Tolerance_%=10%, Value_Code=47R0, ValueDisplayed=47
T1 T2 T3: library part CMP-0030601-1, "Transformer, 340 uH, SMT", Manufacturer="Wurth Elektronik", Supplier Part Number 1=1297-1105-1-ND, ValueDisplayed=340uH
TP2 TP3: library part CMP-0055139-1, "Test Point, Miniature, White, TH", Color=White, Manufacturer=Keystone, Supplier Part Number 1=36-5002-ND
U1 U5 U8: library part CMP-0013494-3, "Small Reinforced Isolated Modulator With +/-50mV Input and CMOS Interface, DWV0008A (SOIC-8)", Alternate Manufacturer="Texas Instruments", Alternate PartNumber=AMC1306M05DWV, Operating Temperature Range="-40 to 125 C", Rating=Catalog
U2 U7 U22: library part CMP-0076095-1, "Low-Noise 1 A, 420 kHz Transformer Driver, DBV0006A (SOT-23-6)", Alternate Manufacturer="Texas Instruments", Alternate PartNumber=SN6505BDBVT
U3 U4 U6: library part CMP-0086107-1, "Current Sensor 15A 1 Channel Flux Gate, Closed Loop Bidirectional Module, TH", Manufacturer=LEM
U9: library part CMP-0041120-1, "Single-Supply, Rail-to-Rail Operational Amplifier MicroAmplifier(TM) Series, 2.7 to 5 V, -40 to 85 degC, 14-pin SOIC (D14), Green (RoHS & no Sb/Br)", Manufacturer="Texas Instruments", Total Supply Voltage(Max)(+5V is 5, +/-5V is 10)=5, Total Supply Voltage(Min)(+5V is 5, +/-5V is 10)=2.7
U10 U21 U23: library part CMP-0035558-1, "Single Output LDO, 150 mA, Fixed 5 V Output, 2.5 to 24 V Input, with Ultra-Low IQ, 5-pin SOT-23 (DBV), -40 to 125 degC, Green (RoHS & no Sb/Br)", Manufacturer="Texas Instruments"
U11: library part CMP-0013938-2, "SIMPLE SWITCHER 3.5V to 60V 3.5A Synchronous Step-Down Voltage Regulator, RNP0030B (WQFN-30)", Alternate Manufacturer="Texas Instruments", Alternate PartNumber=LM76003RNPT
U12: library part CMP-0031048-1, "2.25 A, 4.5 to 18 V Input Wide Adjust Miniature Power Module, -40 to 85 degC, 5-pin Module (EUG5), Pb-Free (RoHS)", Manufacturer="Texas Instruments"
U13 U14 U16: library part CMP-0076507-3, "2.7V-Capable, 10 uA Analog Output Temperature Sensor in SC70 and TO-92, LP0003A (TO-92-3)", Alternate Manufacturer="Texas Instruments", Alternate PartNumber=LMT87LP, Operating Temperature Range="-50 to 150 C", Rating=Catalog
U15: library part CMP-0036760-1, "Single Output LDO, 1 A, Fixed 3.3 V Output, 2 to 5.5 V Input, 4-pin SOT-223 (DCY), -40 to 125 degC, Green (RoHS & no Sb/Br)", Manufacturer="Texas Instruments"
U17: library part CMP-0066236-2, "Automotive Grade, 2.7V-Capable, 10 uA Analog Output Temperature Sensor, DCK0005A (SOT-SC70-5)", Alternate Manufacturer="Texas Instruments", Alternate PartNumber=LMT87QDCKTQ1
U18 U19: library part CMP-0041149-1, "High-Speed, Single-Supply, Rail-to-Rail Operational Amplifier MicroAmplifier(TM) Series, 2.7 to 5.5 V, -55 to 150 degC, 14-pin SOIC (D14), Green (RoHS & no Sb/Br)", Manufacturer="Texas Instruments", Total Supply Voltage(Max)(+5V is 5, +/-5V is 10)=5.5, Total Supply Voltage(Min)(+5V is 5, +/-5V is 10)=2.7
U20: library part CMP-0040936-1, "Single-Supply, Rail-to-Rail Operational Amplifier MicroAmplifier(TM) Series, 2.7 to 5.5 V, -40 to 85 degC, 5-pin SOT23 (DBV5), Green (RoHS & no Sb/Br)", Manufacturer="Texas Instruments", Total Supply Voltage(Max)(+5V is 5, +/-5V is 10)=5.5, Total Supply Voltage(Min)(+5V is 5, +/-5V is 10)=2.7
U24: library part CMP-0066190-1, "Low-Drift, Low-Power, Dual-Output VREF and VREF/2 Voltage Reference, DDC0005A (SOT-23-T-5)", Alternate Manufacturer="Texas Instruments", Alternate PartNumber=REF2033AIDDCT
ZZ1: library part CMP-0003616-3
ZZ2: library part CMP-0077236-1
ZZ3: library part CMP-0077237-1
ZZ4: library part CMP-0077238-1

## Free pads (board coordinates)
  round 314.96 hole 133.86: 1(218.39,205) 1(233.69,7660.01) 1(1451.94,3424) 1(5846,7660) 1(5846,215) 1(10721.47,1026) 1(10721.48,7660) 1(13568.17,7660) 1(13573.17,215)
  oval 20x150 hole 20 slot 150 at 90 deg unplated mask+8: 1(6112.22,908.87) 1(6112.22,2964.94) 1(6112.22,5021) 1(6327.22,908.87) 1(6327.22,2964.94) 1(6327.22,5021) 1(7076,908.87) 1(7076,2964.94) 1(7076,5021) 1(7291,908.87) 1(7291,2964.94) 1(7291,5021) 1(8039.78,908.87) 1(8039.78,2964.94) 1(8039.78,5021) 1(8254.78,908.87) 1(8254.78,2964.94) 1(8254.78,5021) 1(9003.56,908.87) 1(9003.56,2964.94) 1(9003.56,5021) 1(9218.56,908.87) 1(9218.56,2964.94) 1(9218.56,5021)
  oval 300x20 hole 20 slot 300 at 0 deg unplated mask+8: 1(6273.22,503.94) 1(6273.22,2560) 1(6273.22,4616.06) 1(7230,510) 1(7237,2560) 1(7237,4616.06) 1(8200,510) 1(8200,2560) 1(8200.78,4616.06) 1(9160,510) 1(9163.78,2560) 1(9164.56,4616.06)
  oval 150x20 hole 20 slot 150 at 0 deg unplated mask+8: 1(7656.99,2100) 1(7656.99,4150) 1(7660,1337.87) 1(7660,3393.94) 1(7660,5450)

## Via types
v1: diameter 32, hole 16, Top Layer to Bottom Layer, 336 vias
v2: diameter 24, hole 12, Top Layer to Bottom Layer, 140 vias
v3: diameter 50, hole 28, Top Layer to Bottom Layer, tented both sides, 65 vias
v4: diameter 52, hole 28, Top Layer to Bottom Layer, 14 vias
v5: diameter 19.68, hole 7.87, Top Layer to Bottom Layer, 10 vias
v6: diameter 50, hole 28, Top Layer to Bottom Layer, 7 vias

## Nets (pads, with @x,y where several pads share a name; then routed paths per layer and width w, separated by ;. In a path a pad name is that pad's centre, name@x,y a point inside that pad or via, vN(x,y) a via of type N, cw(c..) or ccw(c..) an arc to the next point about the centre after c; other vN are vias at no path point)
1.65V_U9: C131.2 R29.1 R30.1 R33.1 R129.2 | length 1231.2
  Top Layer w20: v1(8839.7,6513) 8840.2,6512.5 R29.1@8885.7,6512.5 ; v1(9122,6320.27) 9122.5,6320.76 R33.1@9122.5,6366.27 ; R30.1@9315.7,6517.5 9422.67,6517.5 9440,6500.18 9440,6383.01 9422.24,6365.24 C131.2@9380.7,6365.24 9379.21,6366.74 R129.2@9379.21,6435.2
  Bottom Layer w25: v1(8839.7,6513) 8929.27,6513 v1(9122,6320.27) 9283.7,6320.27 9361.7,6398.27 v1(9361.7,6517.01)
1.65V_U18: C72.2 R56.1 R78.1 R89.1 R143.2 R179.1 R195.2 | length 2387.4
  Top Layer w20: R143.2@6623.77,6398.5 C72.2@6691.5,6398.5 R179.1@6691.5,6330 6698.63,6322.87 v1(6698.63,6242.89) 6802.89,6242.89 6834.6,6274.6 6908.08,6274.6 6956.68,6226 7158.87,6226 7188.11,6255.24 R78.1@7188.11,6327 7187.11,6326 R56.1@7099.11,6326 ; v1(6874,7100) R195.2@6939.55,7100 7002.71,7100 7146.41,6956.3 R89.1@7146.41,6901
  Bottom Layer w20: v1(6698.63,6242.89) 6698.63,6308.88 6749.75,6360 6872.48,6360 6965.97,6453.49 6965.97,6744.05 6874,6836.02 v1(6874,7100)
1.65V_U19: C70.2 R104.1 R116.1 R127.1 R140.2 R178.1 R196.2 | length 3507.8
  Top Layer w15: v1(8016,7094) 8138.88,7094 8235.75,6997.13 8281.17,6997.13 v1(8327,6951.3)
  Top Layer w20: v1(8052.7,6918) C70.2@8052.7,6869.5 R140.2@8117.7,6869.5 ; R104.1@8279.7,6321 8367.7,6321 R116.1@8368.7,6322 8368.7,6249.62 8368.08,6249 8407.08,6210 8671,6210 8733,6272 8733,6469.85 8555.42,6647.42 v1(8555.42,6781.73) ; R127.1@8327,6896 v1(8327,6951.3)
  Bottom Layer w20: R196.2@7257.46,7640 7257.46,7299.54 7463,7094 v1(8016,7094) ; v1(8052.7,6918) 8086,6951.3 v1(8327,6951.3) 8327,6874 8419.27,6781.73 v1(8555.42,6781.73)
